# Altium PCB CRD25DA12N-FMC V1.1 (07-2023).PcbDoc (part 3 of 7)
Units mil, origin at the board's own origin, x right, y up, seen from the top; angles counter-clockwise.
Board outline 8000 x 8000 mil, 6 copper layers (Top Layer, Layer 2, Layer 3, Layer 4, Layer 5, Bottom Layer), stack 91 mil thick; 542 components, 315 nets, 1585 pads, 558 vias.
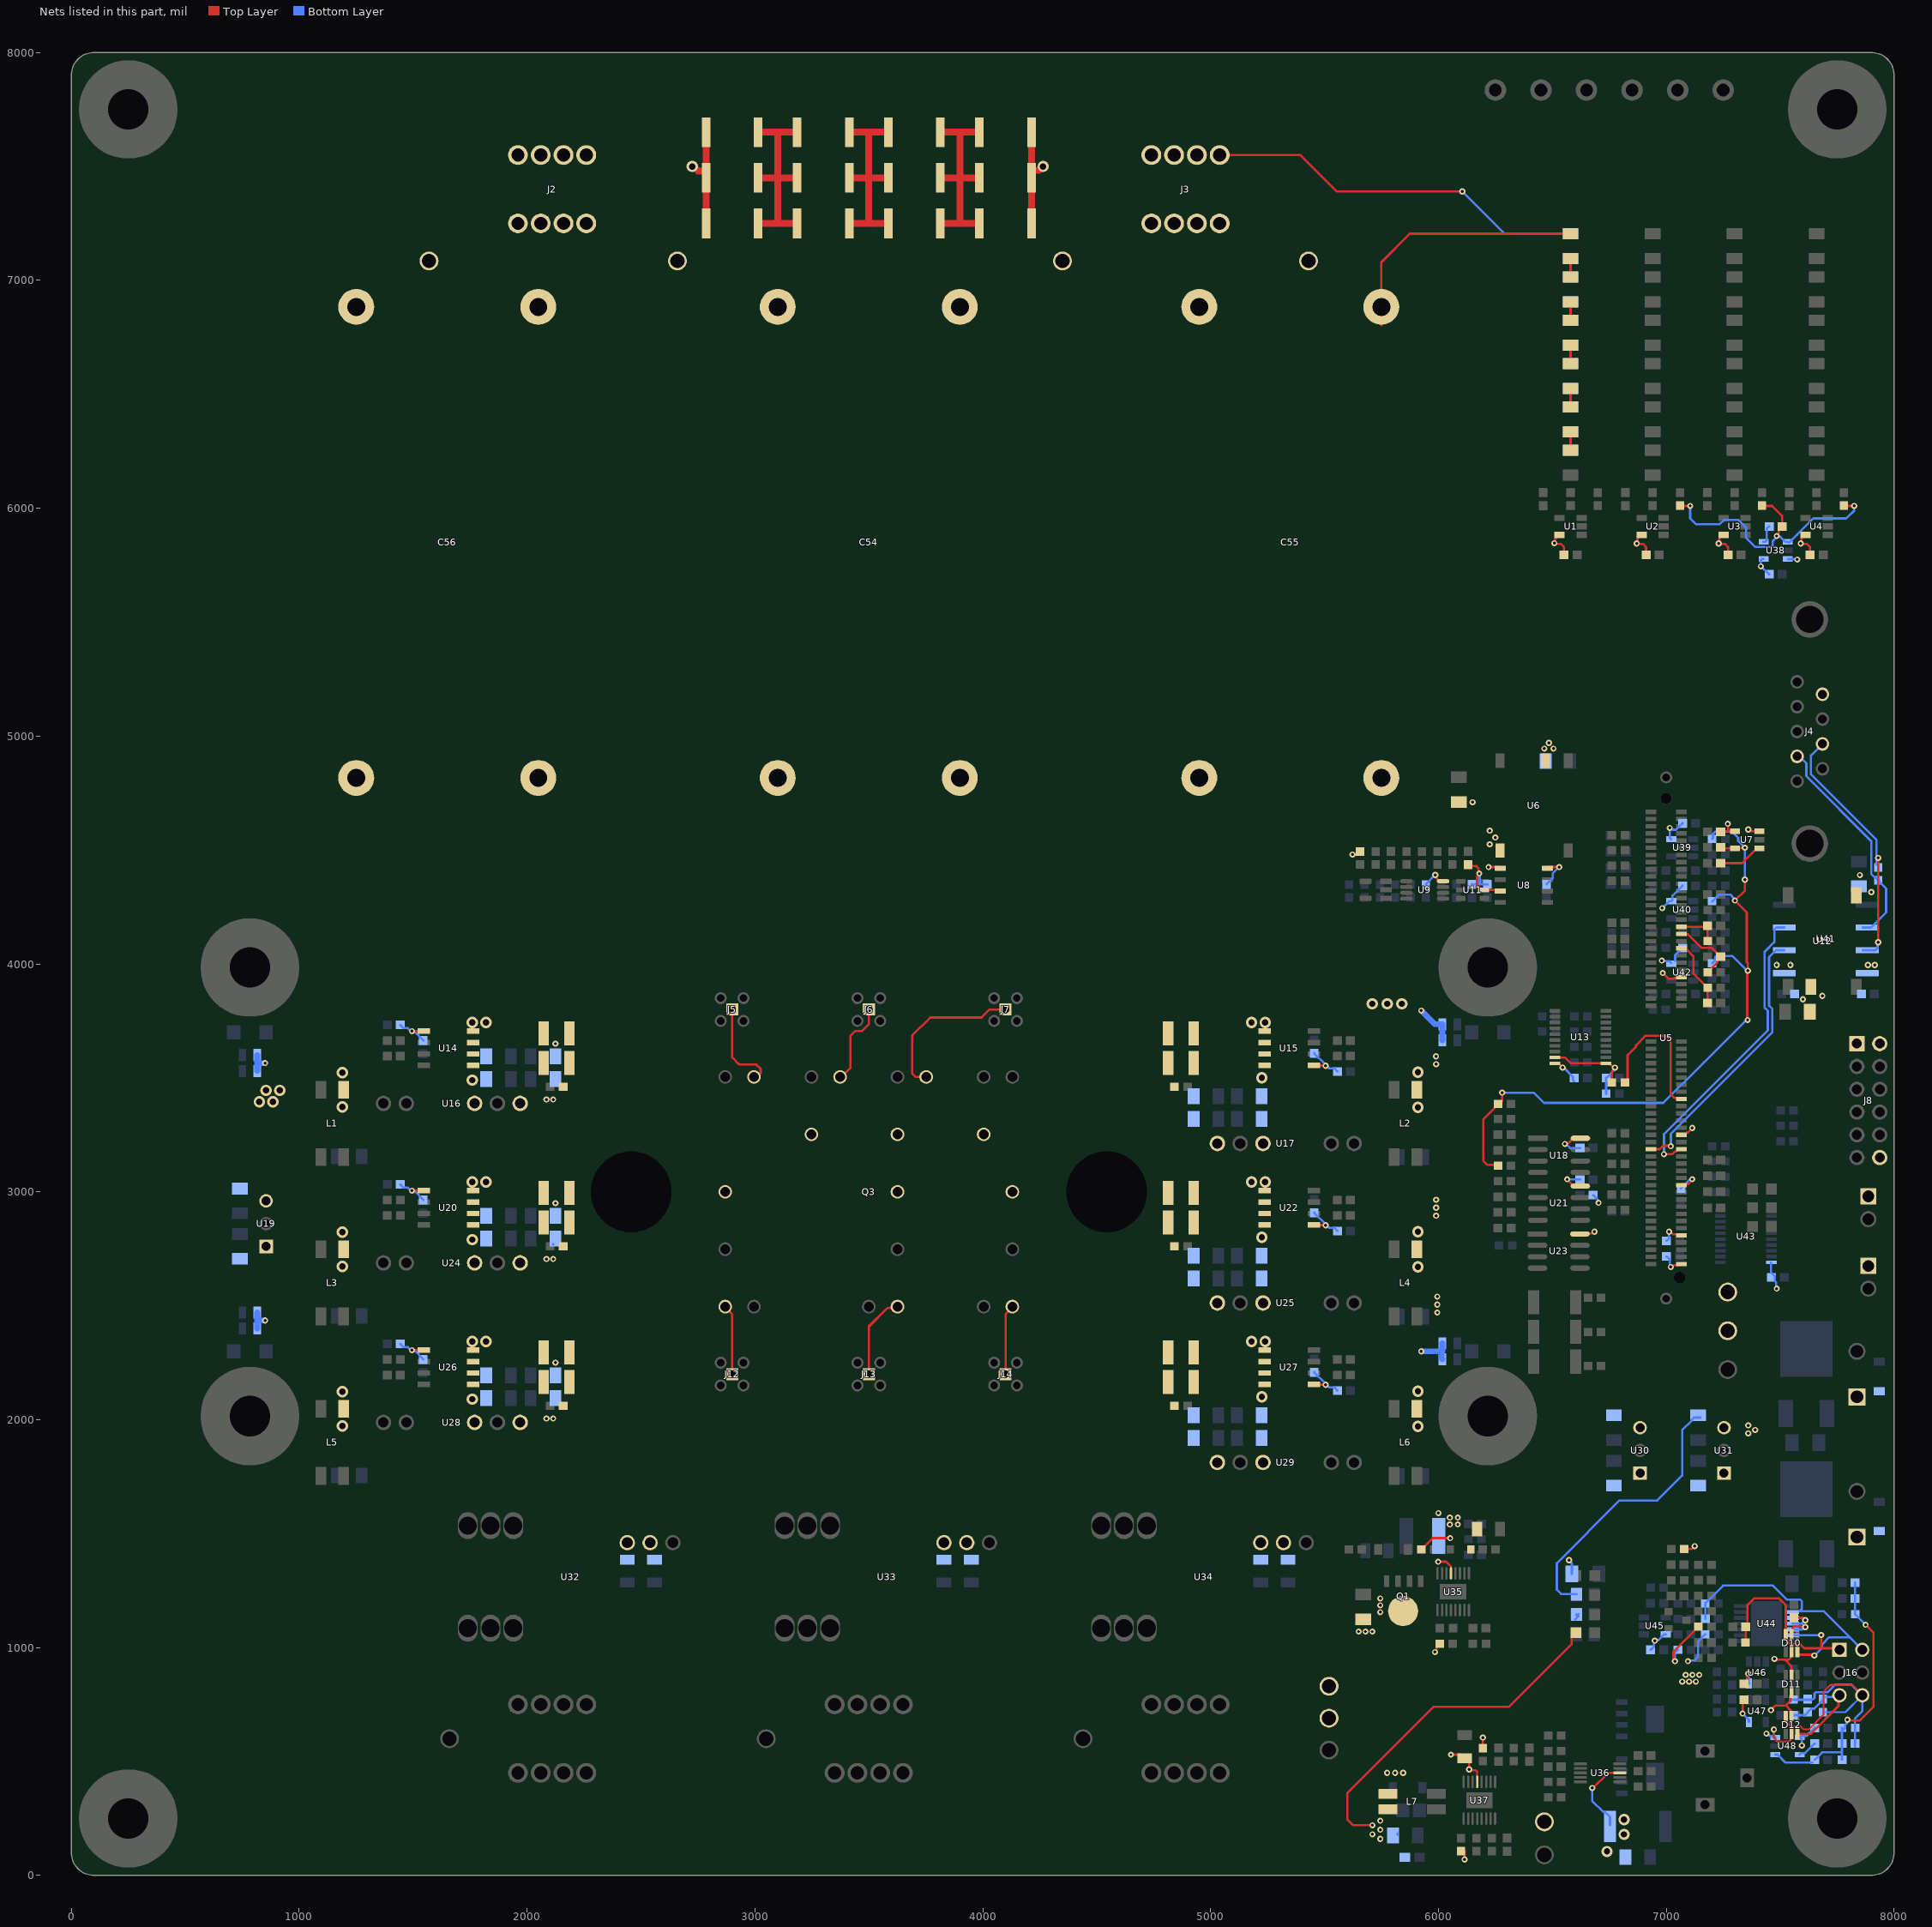
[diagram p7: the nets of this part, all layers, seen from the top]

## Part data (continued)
R212 R217: "RES SMD 15K OHM 0.5% 1/10W 0603", Case Code (Imperial)=0603, Case Code (Metric)=1608, Manufacturer=PANASONIC, Max Operating Temperature=155°C, Max Power Dissipation=100mW, Min Operating Temperature=-55°C, Package Quantity=5000, Power Rating=0.1W, Ratings=AEC-Q200, Resistance=15kΩ, Resistance Tolerance=0.5%, Resistor Type="Thin Film", Supplier Part Number 1=P15KBLCT-ND, Temperature Coefficient=25ppm/°C, Voltage Rating=75V
R213 R216: "RES SMD 2.43K OHM 1% 1/8W 0805", Case Code (Imperial)=0805, Case Code (Metric)=2012, Manufacturer=PANASONIC, Max Operating Temperature=155°C, Max Power Dissipation=125mW, Min Operating Temperature=-55°C, Package Quantity=1, Power Rating=0.13W, Resistance=2.43kΩ, Resistance Tolerance=1%, Resistor Type="Thick Film", Supplier Part Number 1=73AC7648, Temperature Coefficient=100ppm/°C, Voltage Rating=150V
R220 R223 R224 R227: "RES SMD 12.1K OHM 0.1% 1/5W 0603", Case Code (Imperial)=0603, Case Code (Metric)=1608, Manufacturer=PANASONIC, Max Operating Temperature=155°C, Max Power Dissipation=0.2W, Min Operating Temperature=-55°C, Resistance=12.1kΩ, Resistor Type="Thick Film", Supplier Part Number 1=68AC5970, Temperature Coefficient=50ppm/°C, TOLERANCE=0.1%
R221 R225: "RES 47K OHM 1% 1/10W 0603", Case Code (Imperial)=0603, Case Code (Metric)=1608, Manufacturer=YAGEO, Max Operating Temperature=155°C, Max Power Dissipation=100mW, Min Operating Temperature=-55°C, Package Quantity=1, Power Rating=0.1W, Resistance=47kΩ, Resistance Tolerance=1%, Resistor Type="Thick Film", Supplier Part Number 1=6616189, Temperature Coefficient=100ppm/°C, Voltage Rating=50V
R229: "RES 0.01 OHM 1% 2W 2512", Case Code (Imperial)=2512, Case Code (Metric)=6432, Manufacturer=YAGEO, Max Operating Temperature=170°C, Max Power Dissipation=2W, Min Operating Temperature=-55°C, Resistance=10mΩ, Resistor Type="Metal Film", Supplier Part Number 1=1995902P, Temperature Coefficient=50ppm/°C, TOLERANCE=1%
R230: "RES 180K OHM 1% 1/10W 0603", Case Code (Imperial)=0603, Case Code (Metric)=1608, Manufacturer=TE, Max Operating Temperature=155°C, Max Power Dissipation=0.1W, Min Operating Temperature=-55°C, Resistance=180kΩ, Resistor Type="Thick Film", Supplier Part Number 1=73AC9068, Temperature Coefficient=100ppm/°C, TOLERANCE=1%
TP1 TP2 TP5 TP6 TP8 TP9 TP14: library part CMP-1672-00002-4, "PC TEST POINT MULTIPURPOSE RED", Colour=Red, Manufacturer=KEYSTONE, Package=N/A, Package Quantity=100
TP3 TP4 TP7 TP13 TP15: library part CMP-1672-00003-4, "PC TEST POINT MULTIPURPOSE BLACK", Colour=Black, Manufacturer=KEYSTONE, Package=N/A, Package Quantity=100
TP10 TP11 TP12: library part CMP-1672-00004-4, "PC TEST POINT MULTIPURPOSE WHITE", Colour=White, Manufacturer=KEYSTONE, Package=N/A, Package Quantity=100
U1 U2 U3 U4 U39 U40 U42 U45 U46 U47: library part CMP-0384-02059-2, "IC OPAMP GP 1 CIRCUIT TSOT23-5", Amplifiers Per Package=1, Generic Part Number=AD8615, Input Bias Current=200fA, Input Offset Voltage=80uV, Manufacturer="ANALOG DEVICES", Package=TSOT-23-5
U5: "EVAL BOARD FOR TMS320F280039C", Manufacturer="TEXAS INSTRUMENTS", Package=N/A, Supplier Part Number 1=595-TMDSCNCD280039C
U6: library part CMP-2000-07241-1, "DC DC CONVERTER 5V 1W", Input Voltage DC Max=5.5V, Input Voltage DC Min=4.5V, Manufacturer=TRACOPOWER, Output Current Max=200mA, Output Power Max=1W, Output Voltage Nom.=5V, Package=8-SMD, Package Description="5-Pin Surface Mount Device, Body 13.7 x 8.0 mm"
U7 U38 U48: "AUTOMOTIVE LOW-DRIFT, LOW-POWER,", Manufacturer="TEXAS INSTRUMENTS", Supplier Part Number 1=595-REF2033QDDCRQ1
U8: library part CMP-0328-00055-4, "DGTL ISO 2500VRMS 1CH GP 8SOIC", Insulation Rating(VRMS)=2500, Manufacturer="TEXAS INSTRUMENTS", Package=8-SOIC, Rating=Catalog, Supply Voltage(s)(V)="3.3, 5"
U9: "IC OPAMP GP 2 CIRCUIT 8MSOP", Case/Package=MSOP, Input Bias Current=1pA, Input Offset Voltage (Vos)=3mV, Input Offset Voltage-Max=5mV, Manufacturer=MICROCHIP, Max Operating Temperature=125°C, Max Supply Voltage=5.5V, Min Operating Temperature=-40°C, Min Supply Voltage=2.4V, Nominal Supply Current=1mA, Output Current=25mA, Package=8-MSOP, Package Quantity=100, Power Supply Rejection Ratio (PSRR)=70dB, Supplier Part Number 1=20T6022, Voltage Gain=110dB
U10: "IC VREF SHUNT ADJ 2% SOT23-5", Case/Package=SOT-23-5, Cathode Current=60uA, Manufacturer=STMICROELECTRONICS, Manufacturer Print=ST, Max Input Voltage=10V, Max Operating Temperature=125°C, Max Output Current=30mA, Max Output Voltage=6V, Min Operating Temperature=-40°C, Min Output Voltage=1.24V, Package Quantity=1, Temperature Coefficient=100ppm/°C, TOLERANCE=2%
U11: "IC OSC SILICON PROG TSOT23-6", Frequency=3.81Hz, Manufacturer="ANALOG DEVICES", Max Operating Temperature=70°C, Max Supply Voltage=5.5V, Min Operating Temperature=0°C, Min Supply Voltage=2.25V, Operating Supply Current=365uA, Package=TSOT-23-6, Package Quantity=1, Supplier Part Number 1=505-LTC6992CS6-2#TRMPBFDKR-ND
U12: "DC DC CONVERTER 5V 1W", Case/Package=SMD/SMT, Current - Output 1=200mA, Isolation Voltage=2kV, Manufacturer=RECOM, Max Input Voltage=3.63V, Max Operating Temperature=100°C, Max Output Power=1W, Max Output Voltage=5V, Min Input Voltage=2.97V, Min Operating Temperature=-40°C, Package=8-SMD, Supplier Part Number 1=945-R1SE-3.305/H2-RCT-ND
U13 U43: library part CMP-0440-01163-3, "IC BUF NON-INVERT 5.5V 20TSSOP", F @ Nom Voltage(Max)(Mhz)=110, Generic Part Number=SN74LV541AT, ICC @ Nom Voltage(Max)(mA)=0.02, Manufacturer="TEXAS INSTRUMENTS", Operating Temperature Range(C)="-40 to 125", Package=20-TSSOP, Rating=Catalog, tpd @ Nom Voltage(Max)(ns)=7.9, Voltage(Nom)(V)=5
U14 U15 U20 U22 U26 U27: "5A/5A, 3-KVRMS SINGLE-CHANNEL IS", Manufacturer="TEXAS INSTRUMENTS", Max Operating Temperature=125°C, Mfr_Name="Texas Instruments", Min Operating Temperature=-40°C, Package=8-SOIC, Supplier Part Number 1=296-47508-ND, Working Voltage=990V
U16 U17 U24 U25 U28 U29: "DC DC CONVERTER 15V -3V 1.7W", Manufacturer=MURATA, Package=7-SIP, Supplier Part Number 1=580-MGJ2D121503SC
U18 U21 U23: library part CMP-04896-000023-1, "IC COMPARATOR R-R HI-SPD 8-SOIC", Ambient Temperature Range High=+125°C, Ambient Temperature Range Low=-40°C, Input Bias Current=0.000002uA, Input Offset Voltage=1mV, Manufacturer="TEXAS INSTRUMENTS", Max Junction Temp=+150°C, Max Supply Voltage=5.5V, Min Supply Voltage=2.2V, Nominal Supply Current=3.2mA, Package=8-SOIC, Temperature="-40°C to +125°C"
U19 U31: "DC DC CONVERTER 5V 5W", Case/Package=SIP, Current - Output 1=1A, Manufacturer=RECOM, Max Input Voltage=28V, Max Operating Temperature=85°C, Max Output Voltage=5V, Max Power Dissipation=5W, Min Input Voltage=8V, Min Operating Temperature=-40°C, Package=3-SIP, Package Quantity=42, Supplier Part Number 1=1446013
U30: "DC DC CONVERTER 3.3V 3W", Case/Package=SIP, Manufacturer=RECOM, Max Input Voltage=28V, Max Operating Temperature=85°C, Max Output Current=1A, Max Output Power=3.3W, Max Output Voltage=3.3V, Max Power Dissipation=3W, Min Input Voltage=8V, Min Input Voltage (DC)=7V, Min Operating Temperature=-40°C, Package=3-SIP, Supplier Part Number 1=9176626
U32 U33 U34: "SENSOR CURRENT HALL 50A AC/DC", Case/Package=Module, Current Rating=50A, Frequency=200kHz, Manufacturer=LEM, Max Operating Temperature=85°C, Max Supply Current=35mA, Min Operating Temperature=-25°C, Operating Supply Voltage=15V, Package=N/A, Package Quantity=12, Secondary Current=25mA, Supplier Part Number 1=44W8442
U35 U37: "IC REG MULTI CONFG ADJ 16MSOP", Frequency Adjust Range="Up - 2.5MHz", Manufacturer="ANALOG DEVICES", Package=16-TFSOP, Supplier Part Number 1=51AK8743
U36: "IC SURGE SUPPRESSION ADJ 10MSOP", Manufacturer="ANALOG DEVICES", Package=10-MSOP, Supplier Part Number 1=505-LTC4368IMS-2#PBF-ND
U41: "IC TXRX/ISO HALF 1/1 8SOP", Drivers Per Package=1, Manufacturer="TEXAS INSTRUMENTS", Package=8-SOP, Rating=Catalog
U44: library part CMP-04895-000282-1, "IC POWER 2 CIRCUIT 14HTSSOP", Manufacturer="TEXAS INSTRUMENTS", Package=14-PowerTSSOP

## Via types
v1: diameter 27, hole 13, Top Layer to Bottom Layer, tented both sides, 455 vias
v2: diameter 50, hole 28, Top Layer to Bottom Layer, tented both sides, 76 vias
v3: diameter 19.68, hole 7.87, Top Layer to Bottom Layer, 27 vias

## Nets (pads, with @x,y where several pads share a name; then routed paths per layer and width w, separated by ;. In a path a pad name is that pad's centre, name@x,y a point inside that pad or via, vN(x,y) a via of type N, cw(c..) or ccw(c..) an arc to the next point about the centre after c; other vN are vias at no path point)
+1.65V_I: C15.1 U7.1 | length 196.7
  Top Layer w10: C15.1@7238.58,4442 7332.71,4442 7398.31,4507.6 U7.1@7408.15,4507.6
+1.65V_R: C167.1 C168.1 C178.1 C180.1 C181.1 R214.1 R228.1 U48.1 | length 1233.4
  Top Layer w10: v1(7795.11,683.33) 7798.37,680.08 7822.97,680.08 7823.05,680 7850,680 7910,740 7910,1065 v1(7875,1100)
  Bottom Layer w10: U48.1@7478.7,530.2 7488.54,530.2 7523.74,495 C181.1@7642.8,495 ; C181.1@7651.42,508 7652.37,508 7684.37,540 7768.9,540 7771.42,542.52 ; C180.1@7771.42,508 7771.42,542.52 ; R228.1@7771.38,647 R228.1@7771.38,647 R228.1@7771.42,634 ; v1(7795.11,683.33) 7791.86,680.08 7791.86,666.58 7785.24,659.96 7785.24,646.96 7772.28,634 R228.1@7771.42,634 ; C167.1@7828.58,1285 C168.1@7828.58,1215 C168.1@7828.58,1215 R214.1@7828.62,1146 7829.53,1146 7875,1100.53 v1(7875,1100) ; 7771.42,542.52 7771.42,577.05 7770.47,578 C178.1@7771.42,578 R228.1@7771.42,634
+1.65V_V: C5.1 R40.2 R42.2 R44.2 U38.1 | length 1288.1
  Top Layer w10: R40.2@7060,6011.38 7061.38,6010 v1(7105,6010) ; R42.2@7420,6011.38 7421.38,6010 7465,6010 7508.58,5966.42 C5.1@7508.58,5920 7507.63,5920 7493.76,5906.14 7493.76,5891.72 7484.64,5882.6 v1(7484.64,5878) ; R44.2@7780,6011.38 7781.38,6010 v1(7825,6010)
  Bottom Layer w10: v1(7105,6010) 7105,5955 7130,5930 7234.54,5930 7253.04,5948.5 7316.81,5948.5 7350.91,5914.39 7350.91,5869.09 7390.41,5829.59 7459.9,5829.59 7467.25,5836.94 7467.25,5856.01 7484.64,5873.4 v1(7484.64,5878) 7487.9,5874.75 7500.96,5874.75 7523.31,5852.4 U38.1@7533.15,5852.4 ; U38.1@7533.15,5851.2 7541.79,5851.2 7574.09,5883.5 7645.59,5955 7790,5955 7825,5990 v1(7825,6010)
+3.3V: C6.1 C7.1 C8.1 C9.1 C23.1 C46.1 C47.1 C64.1 C73.1 C77.1 C81.1 C83.1 C104.1 C109.1 C114.1 C149.1 C172.1 J8.1 R97.2 R207.1 R217.2 TP5.1 U1.5 U2.5 U3.5 U4.5 U8.8 U12.2 U18.8 U21.8 U23.8 U30.3 U39.5 U40.5 U41.1 U42.5 U45.5 U46.5 U47.5 | length 2098.6
  Top Layer w10: U8.8@6478.35,4425 v1(6530,4425) v1@6532.5,4422.5 ; U1.5@6531.77,5882.6 6522.91,5882.6 6514.13,5873.82 6514.13,5864.96 6511.83,5862.66 6511.83,5849.68 v1(6508.58,5846.42) 6511.14,5843.86 6537.56,5843.86 6551.42,5830 C6.1@6551.42,5795 ; v1(6555,3210) 6558.25,3213.25 6570.07,3213.25 6591.81,3235 U18.8@6623.06,3235 ; v1(6565,3055) 6565,3053.41 6593.41,3025 U21.8@6623.06,3025 U21.8@6651.78,3025 ; U23.8@6621.11,2815 6655.85,2815 6658.32,2817.47 6672.87,2817.47 6680.4,2825 v1(6685,2825) ; U2.5@6891.77,5882.6 6882.91,5882.6 6874.13,5873.82 6874.13,5864.96 6873.25,5864.08 6873.25,5848.25 v1(6870,5845) 6871.14,5843.86 6897.56,5843.86 6911.42,5830 C7.1@6911.42,5795 ; R97.2@7078.62,1432 7111.29,1432 7124.29,1445 v1(7125,1445) ; U3.5@7251.77,5882.6 7242.91,5882.6 7234.13,5873.82 7234.13,5864.96 7233.25,5864.08 7233.25,5848.25 v1(7230,5845) 7231.14,5843.86 7257.56,5843.86 7271.42,5830 C8.1@7271.42,5795 ; v1(7335,710) 7335,764.58 C47.1@7341.42,771 ; C46.1@7341.42,840 7342.37,840 7356.24,853.86 7356.24,876.64 7360,880.4 v1(7360,885) ; U4.5@7611.77,5882.6 7602.91,5882.6 7594.13,5873.82 7594.13,5864.96 7593.25,5864.08 7593.25,5848.25 v1(7590,5845) 7591.14,5843.86 7617.56,5843.86 7631.42,5830 C9.1@7631.42,5795
  Bottom Layer w10: C73.1@6475,4348.58 6475,4349.53 6501.5,4376.03 6501.5,4396.5 v1(6530,4425) ; v1(6555,3210) 6559.31,3210 6577.31,3192 C104.1@6621.42,3192 ; v1(6565,3055) 6620.42,3055 C109.1@6621.42,3054 ; v1(6573.38,1383.08) 6573.38,1381.88 6585.9,1369.37 R207.1@6585.9,1323 ; C114.1@6678.58,2985 6679.53,2985 6699.46,2965.06 6699.46,2954.61 v1(6702.72,2951.35) v1@6699.46,2948.1 ; C172.1@6931.42,990 6932.37,990 6946.24,1003.86 6946.24,1021.64 6950,1025.4 v1(6950,1030) 6953.25,1033.25 6965.02,1033.25 6989.37,1057.6 U45.5@6998.23,1057.6 ; v1(6980.22,4014.95) 6983.47,4011.7 7014.48,4011.7 U42.5@7021.77,4004.4 ; v1(6982.51,4245) 7012.91,4275.4 U40.5@7021.77,4275.4 7027.47,4281.1 7027.47,4300 7070.47,4343 C77.1@7071.42,4343 ; U39.5@7021.77,4547.4 7015.1,4554.07 v1(7015.1,4596.7) 7019.7,4596.7 7027.41,4589 7042.47,4589 7070.47,4617 C64.1@7071.42,4617 ; U42.5@7039.41,4013.18 7039.41,4038.94 7070.47,4070 C81.1@7071.42,4070 ; v1(7095,940) 7098.25,943.25 7123.25,943.25 7140,960 7140,1027.53 7170.47,1058 R217.2@7171.38,1058 ; v1(7335,710) 7362.6,682.4 U47.5@7362.6,673.54 ; v1(7360,885) 7361.3,883.7 7361.3,843.07 U46.5@7362.6,841.77
  other v1: 7600,3845 7685,3860 7485,3995 7545,3995
+3.3V_I: C12.1 R66.2 R71.2 R154.2 R166.2 R172.2 U7.5 | length 3103.2
  Top Layer w10: R71.2@6266.38,3114 6262.07,3118.31 6215,3118.31 6196.5,3136.81 6196.5,3317.03 6265.47,3386 6267.04,3386 6280,3398.96 v1(6280,3435) ; C12.1@7238.58,4511 7241.98,4507.6 U7.5@7301.85,4507.6 7303.05,4508.8 7343.8,4508.8 v1(7345,4510) ; v1(7345,4370) 7345,4322.29 v1(7300.98,4278.27) 7353.5,4225.75 7353.5,4008.5 7357.89,4004.11 v1(7357.89,3970) ; v1@7355,3970 7355,3756.03 v1(7357.21,3753.81)
  Bottom Layer w10: v1(6280,3435) 6418.95,3435 6463.95,3390 6986.9,3390 7162.57,3565.67 7345.25,3748.35 7347.15,3748.35 7352.61,3753.81 v1(7357.21,3753.81) ; R172.2@7201.38,4003 7202.04,4003 7215,4015.96 7215,4029.14 7220.86,4035 7290,4035 7355,3970 v1(7357.89,3970) ; R166.2@7201.38,4275 7202.28,4275 7231.24,4303.96 7282.04,4303.96 7289.11,4296.88 7289.11,4294.74 7300.98,4282.87 v1(7300.98,4278.27) ; R154.2@7201.38,4548 7205,4551.62 7205,4570 7215,4580 7289.69,4580 7315.72,4553.97 7315.72,4539.28 v1(7345,4510) v1(7345,4370)
+3.3V_R: C179.1 U48.5 | length 86.2
  Bottom Layer w10: U48.5@7585,530.2 7591.81,537.01 7609.48,537.01 7650.47,578 C179.1@7651.42,578
+3.3V_V: C61.1 U38.5 | length 82
  Bottom Layer w10: U38.5@7426.85,5852.4 7434.01,5852.4 7440.82,5859.21 7440.82,5909.4 C61.1@7451.42,5920
+5V: C11.1 C62.1 C63.1 C88.1 C93.1 C95.1 C111.1 C117.1 C124.1 C126.1 C129.1 C132.1 C140.1 C145.1 C148.1 C177.1 J8.2 R210.2 TP6.1 U5.48 U5.84 U5.98 U5.112 U5.120 U6.2 U7.3 U7.4 U13.20 U15.1 U22.1 U27.1 U31.3 U38.3 U38.4 U43.20 U48.3 U48.4 | length 2982.5
  Top Layer w10: U27.1@5453.27,2155 5454.37,2153.9 5503.9,2153.9 v1(5505,2152.8) ; U22.1@5453.27,2855 5454.37,2853.9 5503.9,2853.9 v1(5505,2852.8) ; U15.1@5453.27,3555 5454.37,3553.9 5503.9,3553.9 v1(5505,3552.8) ; U13.20@6510.59,3563.82 6526.34,3563.82 6536.9,3553.25 6546.75,3553.25 v1@6550,3550 ; v1(6984.55,3959.95) 6985.18,3959.95 7009.51,3935.62 7033.12,3935.62 7035.37,3937.87 7062.09,3937.87 U5.48@7066.93,3942.72 ; v1(7012.3,2825) 7016.9,2825 7028.31,2813.59 7062.19,2813.59 U5.112@7066.93,2808.86 ; 7032.63,2678.03 7062.09,2678.03 U5.120@7066.93,2682.87 ; U5.98@7066.93,3029.33 7071.77,3034.17 7096.74,3034.17 7114.05,3051.49 v1(7114.05,3055.34) ; U5.84@7066.93,3249.8 7080.71,3249.8 7091.36,3260.46 7095.11,3260.46 7114.05,3279.4 v1(7114.05,3280) ; C11.1@7238.58,4580 7240.98,4582.4 7271.41,4582.4 ; v1(7270,4615) 7271.41,4613.59 7271.41,4582.4 ; U7.4@7301.85,4582.4 7271.41,4582.4 ; v1(7360,4590) 7364.6,4590 7372.2,4582.4 U7.3@7408.15,4582.4
  Bottom Layer w10: C140.1@5455,2208.42 5455,2207.47 5501.75,2160.73 5501.75,2156.05 v1(5505,2152.8) 5509.6,2152.8 5520.53,2141.86 5542.56,2141.86 C145.1@5556.42,2128 ; C117.1@5455,2908.42 5455,2907.47 5501.75,2860.73 5501.75,2856.05 v1(5505,2852.8) 5509.6,2852.8 5520.53,2841.86 5542.56,2841.86 C124.1@5556.42,2828 ; C88.1@5455,3608.42 5455,3607.47 5501.75,3560.73 5501.75,3556.05 v1(5505,3552.8) 5509.6,3552.8 5520.53,3541.86 5542.56,3541.86 C93.1@5556.42,3528 ; v1(6545,3545) 6548.25,3541.75 6553.73,3541.75 6590,3505.47 6590,3490 C95.1@6595,3485 ; R210.2@6606.54,1234 6605.54,1235 6538.57,1235 6520,1253.57 6520,1370 6795,1645 6960,1645 7070,1755 7070,1954.14 7110.39,1994.53 7110.39,1998.49 7121.09,2009.19 C148.1@7150,2009.19 ; C129.1@7001.42,2716 7002.37,2716 7016.24,2702.14 7016.24,2678.36 7020,2674.6 v1(7020,2670) ; C126.1@7001.42,2785 7012.3,2795.88 v1(7012.3,2825) ; C111.1@7065,3015 7065,3015.95 7101.14,3052.09 7110.8,3052.09 v1(7114.05,3055.34) ; U38.4@7426.85,5777.6 7421.81,5777.6 7415,5770.79 v1(7415,5745) 7415.47,5745 7450.47,5710 C62.1@7451.42,5710 ; v1(7439.83,622.32) 7444.43,622.32 7454.93,611.81 7471.89,611.81 U48.3@7478.7,605 ; U43.20@7459.41,2688.82 7459.41,2647.05 7476.24,2630.22 7476.24,2608.36 7481.75,2602.85 7481.75,2578.25 v1(7485,2575) ; U38.3@7533.15,5777.6 7534.45,5776.3 7573.7,5776.3 v1(7575,5775) ; v1(7595,570) 7595,598.19 7588.19,605 U48.4@7585,605 7591.81,611.81 7615.28,611.81 7650.47,647 C177.1@7651.42,647
  other v1: 7360,1940 7390,1955 7360,1975 5995,2470 5995,2505 5995,2540 5990,2895 5990,2930 5990,2965 5990,3560 5989.18,3594.18 6465,4945 6505,4945 6485,4970
+5V_ALT: C87.1 C89.1 C110.1 C112.1 C118.1 C137.1 C141.1 U14.1 U19.3 U20.1 U26.1 | length 546.2
  Top Layer w10: v1(1495,2305) U26.1@1546.73,2305 ; v1(1495,3005) U20.1@1546.73,3005 ; v1(1495,3705) U14.1@1546.73,3705
  Bottom Layer w10: C137.1@1443.58,2332 1457.44,2318.14 1477.26,2318.14 1490.4,2305 v1(1495,2305) 1498.25,2301.75 1507.78,2301.75 1545,2264.53 C141.1@1545,2263.58 ; C110.1@1443.58,3032 1457.44,3018.14 1477.26,3018.14 1490.4,3005 v1(1495,3005) 1498.25,3001.75 1507.78,3001.75 1545,2964.53 C118.1@1545,2963.58 ; C87.1@1443.58,3732 1457.44,3718.14 1477.26,3718.14 1490.4,3705 v1(1495,3705) 1498.25,3701.75 1507.78,3701.75 1545,3664.53 C89.1@1545,3663.58
+5V_ISO: C67.1 C82.1 J4.9 U12.5 U41.8
  other v1: 7885,3995 7915,3995 7900,4315 7850,4390
+5V_NTC: C10.1 C14.1 C74.1 C75.1 R47.2 R158.2 U6.5 U8.1 U8.3 U9.8 U11.5 | length 559.2
  Top Layer w10: v1@5615,4480 5643.04,4480 5656,4492.96 R47.2@5656,4493.62 ; v1(5986.01,4390.54) 5989.26,4387.28 5989.26,4378.22 6004.1,4363.39 U9.8@6012.4,4363.39 ; C14.1@6130,4436.42 6136.42,4430 6165,4430 6176.24,4418.76 6176.24,4399.52 v1(6179.07,4396.68) 6179.07,4392.08 6169.51,4382.52 6169.51,4346.83 6191.34,4325 U8.3@6271.65,4325 ; v1(6220,4425) U8.1@6271.65,4425
  Bottom Layer w10: R158.2@5945,4348.62 5945,4349.53 v1(5986.01,4390.54) ; C75.1@6147,4348.58 6181,4348.58 ; v1(6179.07,4396.68) 6181,4394.76 6181,4348.58 ; C74.1@6215,4348.58 6181,4348.58
  other v1: 5623,4480 6225,4525 6250,4555 6225,4585 6150,4710
+12V: C37.1 C48.1 C125.1 C154.1 C155.1 C184.1 D5.2 D17.1 D18.1 J8.12 J9.1 J10.1 J11.1 J15.1 L1.1 L2.1 L3.1 L4.1 L5.1 L6.1 L7.1 L8.1 R99.2 R108.2 R112.2 R119.2 R178.2 R183.2 R185.2 R188.2 R200.2 R201.2 R202.2 R203.2 R229.2 TP14.1 U19.1 U30.1 U31.1 U35.5 U36.8 U37.5 | length 1480.6
  Top Layer w8: 6048.25,1362.83 6055,1356.08 U35.5@6055,1350 ; U37.5@6169.84,409.25 6169.84,455 ; 6745,449.84 U36.8@6797.09,449.84
  Top Layer w10: R99.2@5925,1430 5925.91,1430 5975.91,1480 v1(6051.5,1480) ; v1(5985,980) 5985,984.6 5991.93,991.53 5991.93,1004.04 6004.88,1017 R108.2@6005.79,1017 ; v1(5998.61,1376.66) 6034.42,1376.66 6048.25,1362.83 ; v1(6055,530) 6100.36,530 6135,495.36 v1(6135,465) 6138.25,461.75 6163.1,461.75 6169.84,455 ; v1(6115,70) R119.2@6115,107.95 ; C37.1@6166.82,1520 C37.1@6166.82,1527.91 ; R112.2@6195,560.79 v1(6195,605) ; v1(6674.85,383.5) 6678.66,383.5 6745,449.84
  Bottom Layer w10: v1(6674.85,383.5) 6674.85,327.3 6724.07,278.08 6731.14,278.08 6752.87,256.34 R229.2@6752.87,220
  Bottom Layer w25: R201.2@815.95,2400 815.95,2435 ; R200.2@815.95,2470 815.95,2435 ; R188.2@815.95,3530 815.95,3565 ; R185.2@815.95,3600 815.95,3565 ; v1(850,2435) 815.95,2435 ; v1(850,3565) 815.95,3565 ; v1(5925,2300) 6017.52,2300 R202.2@6017.52,2335 ; v1(5925,3795) 5985,3735 R178.2@6017.52,3735 R183.2@6017.52,3665 ; 6013.29,2307.34 6013.29,2269.23 R203.2@6017.52,2265
  other v1: 5775,450 5810,450 5845,450 6050,1540 6085,1540 6050,1570 6085,1570 6000,1590
  other v2: 6740,105 6815,180 6815,245 5910,1970 1190,1972 1190,2123 5910,2125 5910,2670 1190,2672 1190,2823 5910,2825 5910,3370 1190,3372 825,3395 885,3395 855,3445 915,3445 1190,3523 5910,3525 5710,3825 5775,3825 5840,3825
+15V: C40.1 C42.1 C161.1 C163.1 C165.1 D10.2 D10.5 D11.2 D11.5 D12.2 D12.5 Q1.5-6-7-8 R105.2 R213.2 R219.2 TP8.1 U32.8 U33.8 U34.8 U44.10 U44.11 U44.12 | length 1183
  Top Layer w10: C40.1@5655,1105 C40.1@5670,1120 ; v1(7038,940) 7034.75,943.25 7034.75,950.25 7031.78,953.22 7031.78,982.31 7140.47,1091 R105.2@7141.38,1091 ; v1(7459.43,725.36) 7479.79,745.72 7525.11,745.72 ; v1(7472.16,640.31) 7472.16,604.54 7489.7,586.99 7537.82,586.99 7546.14,595.31 7546.14,616.77 D12.2@7550,620.63 ; v1(7475,950) 7478.01,946.99 7519,946.99 7520,945.99 ; D12.5@7550,699.37 7546.14,703.23 7546.14,724.69 7525.11,745.72 ; D11.2@7550,800.63 7546.14,796.77 7546.14,766.75 7525.11,745.72 ; D11.5@7550,879.37 7549.98,917.01 7520,946.99 7537.82,946.99 7546.14,955.31 7546.14,976.77 D10.2@7550,980.63 ; D10.5@7550,1059.37 7553.86,1063.23 7553.86,1084.69 7562.18,1093.01 7589.01,1093.01 7590.51,1091.5 7608.5,1091.5 v1(7610,1090) ; C42.1@7560,1131.42 7593.98,1131.42 7605.4,1120 v1(7610,1120)
  Bottom Layer w10: R213.2@6600.79,1123.43 6614.49,1137.13 R213.2@6614.49,1145 ; R213.2@6606.54,1140.98 R213.2@6606.54,1145 ; v1(7038,940) 7038,977.04 7050.96,990 R219.2@7051.38,990 ; U44.12@7554.17,1079.41 7597.69,1079.41 7608.28,1090 v1(7610,1090) 7595,1105 ; U44.11@7554.17,1105 7595,1105 ; U44.10@7555.91,1128.86 U44.10@7554.17,1130.59 7596.29,1130.59 7606.88,1120 v1(7610,1120) 7595,1105
  other v1: 7070,850 7100,850 7130,850 7085,880 7115,880 7145,880 5650,1070 5680,1070 5710,1070 5745,1155 5745,1185 5745,1215
+15V_U_HS: C122.1 C127.1 U20.5 U24.7 | length 1.1
  Bottom Layer w10: C127.1@2114.19,2770 C127.1@2115,2769.19
  other v1: 2085,2705 2115,2705 2125,2950
  other v2: 1760,2790
+15V_U_LS: C143.1 C146.1 U26.5 U28.7
  other v1: 2085,2005 2115,2005 2125,2250
  other v2: 1760,2090
+15V_V_HS: C91.1 C96.1 U14.5 U16.7
  other v1: 2085,3405 2115,3405 2125,3650
  other v2: 1760,3490
+15V_V_LS: C151.1 C153.1 U27.5 U29.7
  other v2: 5180,2342.8 5240,2342.8
+15V_W_HS: C99.1 C101.1 U15.5 U17.7
  other v2: 5180,3742.8 5240,3742.8
+15V_W_LS: C131.1 C134.1 U22.5 U25.7
  other v2: 5180,3042.8 5240,3042.8
-3V_U_HS: C123.2 C128.2 U20.8 U24.5
  other v2: 1760,3042.8 1820,3042.8
-3V_U_LS: C144.2 C147.2 U26.8 U28.5
  other v2: 1760,2342.8 1820,2342.8
-3V_V_HS: C92.2 C97.2 U14.8 U16.5
  other v2: 1760,3742.8 1820,3742.8
-3V_V_LS: C150.2 C152.2 U27.8 U29.5
  other v2: 5225,2100
-3V_W_HS: C98.2 C100.2 U15.8 U17.5
  other v2: 5225,3500
-3V_W_LS: C130.2 C133.2 U22.8 U25.5
  other v2: 5225,2800
-15V: C162.2 C164.2 C166.2 C183.1 D9.1 L7.2 R230.2 TP9.1 U32.7 U33.7 U34.7 | length 1556.3
  Top Layer w10: v1(5710,220) 5625,220 5600,245 5600,360 5980,740 6310,740 6585.04,1015.04 6585.04,1046.38 D9.1@6603.66,1065
  Bottom Layer w10: C183.1@5821.88,178.06 C183.1@5821.88,185
  other v1: 5745,160 5710,180 5745,200 5745,240
A14: C20.1 R58.2 U5.36 | length 304.8
  Top Layer w10: U5.36@7066.93,4131.69 7068.62,4130 7095,4130 7153.96,4071.04 7198.58,4071.04 C20.1@7237.63,4032 ; R58.2@7181.38,3964 7182.28,3964 7223.76,4005.48 7223.76,4018.14 C20.1@7237.63,4032 ; C20.1@7238.58,4032 C20.1@7237.63,4032
BLEED1: R1.1 R2.2 R5.1 R6.2 R9.1 R10.2 | length 914.5
  Top Layer w30: R9.1@3014.25,7250 3100,7250 ; R5.1@3014.25,7450 3100,7450 ; R1.1@3014.25,7650 3100,7650 ; R10.2@3185.75,7250 3100,7250 ; R6.2@3185.75,7450 3100,7450 ; R2.2@3185.75,7650 3100,7650 ; 3100,7250 3100,7450 ; 3100,7450 3100,7650
BLEED2: R2.1 R3.2 R6.1 R7.2 R10.1 R11.2 | length 914.5
  Top Layer w30: R10.1@3414.25,7250 3500,7250 ; R6.1@3414.25,7450 3500,7450 ; R2.1@3414.25,7650 3500,7650 ; R11.2@3585.75,7250 3500,7250 ; R7.2@3585.75,7450 3500,7450 ; R3.2@3585.75,7650 3500,7650 ; 3500,7250 3500,7450 ; 3500,7450 3500,7650
BLEED3: R3.1 R4.2 R7.1 R8.2 R11.1 R12.2 | length 914.5
  Top Layer w30: R11.1@3814.25,7250 3900,7250 ; R7.1@3814.25,7450 3900,7450 ; R3.1@3814.25,7650 3900,7650 ; R12.2@3985.75,7250 3900,7250 ; R8.2@3985.75,7450 3900,7450 ; R4.2@3985.75,7650 3900,7650 ; 3900,7250 3900,7450 ; 3900,7450 3900,7650
C14: C22.1 R59.2 U5.40 | length 298.9
  Top Layer w10: U5.40@7066.93,4068.7 7071.77,4063.86 7089.3,4063.86 7118.68,4034.47 7118.68,3957.79 7180.47,3896 R59.2@7181.38,3896 R59.2@7181.38,3896 C22.1@7181.42,3828
CAN_H: J4.7 R156.2 U41.7 | length 1136
  Top Layer w10: v1(7930,4095) v1(7930,4465)
  Bottom Layer w10: J4.7@7685.91,4965.47 7635,4914.57 7635,4832.46 7922.04,4545.42 R156.2@7922.04,4435.67 ; U41.7@7862.09,4060 U41.7@7882.09,4060 7918.5,4060 7927.28,4068.78 7927.28,4092.28 v1(7930,4095)
CAN_L: J4.2 R156.1 U41.6 | length 981.9
  Bottom Layer w10: J4.2@7574.09,4910.94 7584.06,4910.94 7615,4880 7615,4824.18 7900,4539.18 7900,4395 7914.76,4380.24 7917.04,4380.24 7930,4367.28 R156.1@7930,4366.38 ; U41.6@7862.09,4160 7898.5,4160 7965,4226.5 7965,4330.47 7935,4360.47 R156.1@7935,4366.38
CAN_RX: U5.87 U41.2 | length 1193.4
  Top Layer w10: U5.87@6933.07,3186.81 6971.51,3186.81 6986.54,3201.85 7018.15,3201.85 v1(7020.04,3199.96)
  Bottom Layer w10: v1(7020.04,3199.96) 7020.04,3255.04 7465.71,3700.71 7465.71,3802.42 7451.5,3816.64 7451.5,4030 7481.5,4060 U41.2@7517.91,4060
CAN_TX: U5.88 U41.3 | length 1331.6
  Top Layer w10: v1(6990,3165) 7025.39,3165 7036.54,3176.16 7042.5,3176.16 7053.15,3186.81 U5.88@7066.93,3186.81
  Bottom Layer w10: v1(6990,3165) 6990,3253.28 7445.71,3709 7445.71,3794.14 7431.5,3808.35 7431.5,4051.99 7474.65,4095.14 7474.65,4151.22 7483.43,4160 U41.3@7517.91,4160
COS: C18.1 R56.2 U5.34 | length 177.7
  Top Layer w10: U5.34@7066.93,4163.19 C18.1@7176.61,4163.19 ; R56.2@7181.38,4100 C18.1@7181.42,4168 C18.1@7181.42,4168
COS_N: C175.2 C178.2 D12.6 J16.6 R224.1 R225.1 R228.2 | length 1329.6
  Top Layer w8: 7528.27,673.3 7547.3,654.27 7589.01,654.27 7602.64,640.63 7625,640.63 7690,705.63 7690,805 7720.5,835.5 7814.5,835.5 J16.6@7860,790
  Top Layer w10: D12.6@7524.41,699.37 7524.41,685.59 7528.27,681.73 7528.27,673.3
  Bottom Layer w8: R225.1@7688,716.38 7786.38,716.38 J16.6@7860,790
  Bottom Layer w10: R224.1@7558.62,771 7636.02,771 7638.59,773.58 7644.89,773.58 7650.75,779.43 7650.75,797.62 7656.61,803.48 7707.73,803.48 7740.74,836.5 7813.5,836.5 J16.6@7860,790 7860,720.55 7828.62,689.17 R228.2@7828.62,647 7828.62,634 7828.58,633.96 C178.2@7828.58,565
COS_P: C175.1 D12.3 J16.5 R225.2 R227.1 | length 520.5
  Top Layer w10: D12.3@7575.59,620.63 7633.11,620.63 7755.98,743.5 7755.98,785.98 J16.5@7760,790
  Bottom Layer w10: R227.1@7558.62,703 7608.58,703 7622,716.42 7622,717.37 7635.86,731.24 7648.52,731.24 7690,772.72 R225.2@7690,773.62 ; R225.2@7688,773.62 7688,774.53 7696.96,783.48 7753.48,783.48 J16.5@7760,790
DC+: C54.1 C54.2 C55.1 C55.2 C56.1 C56.2 J2.1 J2.2 J2.3 J2.4 J2.5 J2.6 J2.7 J2.8 Q3.DC+_1 Q3.DC+_2 Q3.DC+_3 R1.2 R5.2 R9.2 R13.1 TP1.1 TP2.1 | length 1654.8
  Top Layer w10: 5749.61,6803.46 5749.61,7079.61 5875,7205 6325,7205 6325.12,7205.12 R13.1@6580,7205.12
  Top Layer w30: v2(2725,7500) 2730.41,7500 2751.32,7479.09 2781.89,7479.09 2785.75,7475.23 R5.2@2785.75,7450 ; R9.2@2785.75,7250 R5.2@2785.75,7450 ; R1.2@2785.75,7650 R5.2@2785.75,7450
DC+1: R13.2 R17.1 | length 79.8
  Top Layer w10: R17.1@6580,7015.12 R13.2@6580,7094.88
DC+2: R17.2 R21.1 | length 79.8
  Top Layer w10: R21.1@6580,6825.12 R17.2@6580,6904.88
DC+3: R21.2 R25.1 | length 79.8
  Top Layer w10: R25.1@6580,6635.12 R21.2@6580,6714.88
DC+4: R25.2 R29.1 | length 79.8
  Top Layer w10: R29.1@6580,6445.12 R25.2@6580,6524.88
DC+5: R29.2 R33.1 | length 79.8
  Top Layer w10: R33.1@6580,6255.12 R29.2@6580,6334.88
DC-: C54.3 C54.4 C55.3 C55.4 C56.3 C56.4 J3.1 J3.2 J3.3 J3.4 J3.5 J3.6 J3.7 J3.8 Q3.DC-1 Q3.DC-2 Q3.DC-3 R4.1 R8.1 R12.1 R125.1 TP3.1 TP4.1 | length 2171.4
  Top Layer w10: J3.4@5040,7550 5395,7550 5555,7390 v1(6105,7390)
  Top Layer w30: R12.1@4214.25,7250 R8.1@4214.25,7450 ; R4.1@4214.25,7650 R8.1@4214.25,7450 ; v2(4265,7500) 4248.11,7483.11 4218.11,7483.11 4214.25,7479.25 R8.1@4214.25,7450
  Bottom Layer w10: v1(6105,7390) 6289.88,7205.12 R125.1@6580,7205.12
DC-1: R125.2 R129.1 | length 79.8
  Bottom Layer w10: R129.1@6580,7015.12 R125.2@6580,7094.88
DC-2: R129.2 R133.1 | length 79.8
  Bottom Layer w10: R133.1@6580,6825.12 R129.2@6580,6904.88
DC-3: R133.2 R137.1 | length 79.8
  Bottom Layer w10: R137.1@6580,6635.12 R133.2@6580,6714.88
DC-4: R137.2 R141.1 | length 79.8
  Bottom Layer w10: R141.1@6580,6445.12 R137.2@6580,6524.88
DC-5: R141.2 R145.1 | length 79.8
  Bottom Layer w10: R145.1@6580,6255.12 R141.2@6580,6334.88
EXC_N: C170.2 D10.3 J16.2 R211.2 U44.9 | length 1227
  Top Layer w10: D10.3@7575.59,980.63 7575.59,972.36 7579.45,968.5 7641.9,968.5 7645.4,965 v1(7650,965)
  Bottom Layer w10: C170.2@7171.42,1126 R211.2@7171.38,1194 R211.2@7171.38,1194 7184.33,1206.96 7185.24,1206.96 7250.13,1271.84 7468.16,1271.84 7530,1210 7587.99,1210 7594.7,1203.29 7594.7,1169.5 7585.24,1160.04 7689.96,1160.04 7805,1045 ; v1(7650,965) 7684.13,999.13 7684.13,1014.13 7715,1045 7805,1045 ; J16.2@7860,990 7805,1045
EXC_P: C43.2 D10.6 J16.1 R107.2 U44.13 | length 952.4
  Top Layer w10: R107.2@7348.62,1022 C43.2@7348.58,1091 C43.2@7348.58,1091 7356.42,1098.84 7356.42,1186.47 7386.4,1216.46 7493.6,1216.46 7520,1190.05 7520,1190 7524.41,1185.59 7524.41,1060 7528.27,1056.14 7528.27,1034.05 7548.05,1014.27 7589.01,1014.27 7606.45,996.82 7753.18,996.82 J16.1@7760,990 ; 7679.82,998.5 7680,998.68 v1(7680,1055)
  Bottom Layer w10: U44.13@7558.03,1057.68 U44.13@7554.17,1053.82 7678.82,1053.82 v1(7680,1055)
G1: J5.1 Q3.G1 R75.2 R82.2 R231.2 | length 412.6
  Top Layer w10: J5.1@2900.39,3800 2900.39,3589.61 2930,3560 2931.48,3560 2932.86,3558.62 3006.38,3558.62 3025,3540 3025,3520 3008.94,3503.94 Q3.G1@2996.06,3503.94 Q3.G1@2995,3505
G1H: R82.1 U20.6
G1L: R75.1 U20.7
G2: J12.1 Q3.G2 R89.2 R95.2 R234.2 | length 308.6
  Top Layer w10: Q3.G2@2870.08,2496.06 2870.08,2493.05 2900.39,2462.74 J12.1@2900.39,2200
G2H: R89.1 U26.6
G2L: R95.1 U26.7
G3: J6.1 Q3.G3 R61.2 R63.2 R232.2 | length 368.9
  Top Layer w10: Q3.G3@3374.02,3503.94 3378.94,3503.94 3420,3545 3420,3685 3440,3705 3470,3705 3500,3735 3500,3799.61 J6.1@3500.39,3800
G3H: R63.1 U14.6
G3L: R61.1 U14.7
G4: J13.1 Q3.G4 R88.2 R96.2 R235.2 | length 370.6
  Top Layer w10: J13.1@3500.39,2200 3500.39,2408.91 3580.98,2489.5 3619.42,2489.5 Q3.G4@3625.98,2496.06
G4H: R88.1 U27.6
G4L: R96.1 U27.7
G5: J7.1 Q3.G5 R60.2 R64.2 R233.2 | length 691.7
  Top Layer w10: Q3.G5@3751.97,3503.94 3706.06,3503.94 3690,3520 3690,3685 3770,3765 3995,3765 4030,3800 J7.1@4100.39,3800
G5H: R60.1 U15.6
G5L: R64.1 U15.7
G6: J14.1 Q3.G6 R74.2 R83.2 R236.2 | length 308.3
  Top Layer w10: J14.1@4100.39,2200 4100.39,2461.95 4129.92,2491.48 Q3.G6@4129.92,2496.06
G6H: R74.1 U22.6
G6L: R83.1 U22.7
GD_DIS: R65.1 U5.74 | length 651.2
  Top Layer w10: R65.1@6818.62,3480 6830,3491.38 6830,3600 6867.45,3637.45 6867.45,3642.65 6909.8,3685 6988.42,3685 6989.92,3683.5 6996.81,3683.5 7020,3660.31 7020,3427.61 7035.48,3412.13 7062.09,3412.13 U5.74@7066.93,3407.28
GD_DIS_FILT: C94.1 R65.2 R189.2 U13.1 U13.19 | length 479.6
  Top Layer w10: U13.19@6510.59,3589.41 6555.59,3589.41 6581.18,3563.82 6750.75,3563.82 v1@6766.31,3548.25 ; R65.2@6761.38,3480 6761.38,3526.78 6775,3540.4 v1(6775,3545)
  Bottom Layer w10: R189.2@6736.38,3430 C94.1@6736.42,3500 C94.1@6736.42,3500 6737.37,3500 6771.75,3534.37 6771.75,3541.75 v1(6775,3545) v1@6775,3540.4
